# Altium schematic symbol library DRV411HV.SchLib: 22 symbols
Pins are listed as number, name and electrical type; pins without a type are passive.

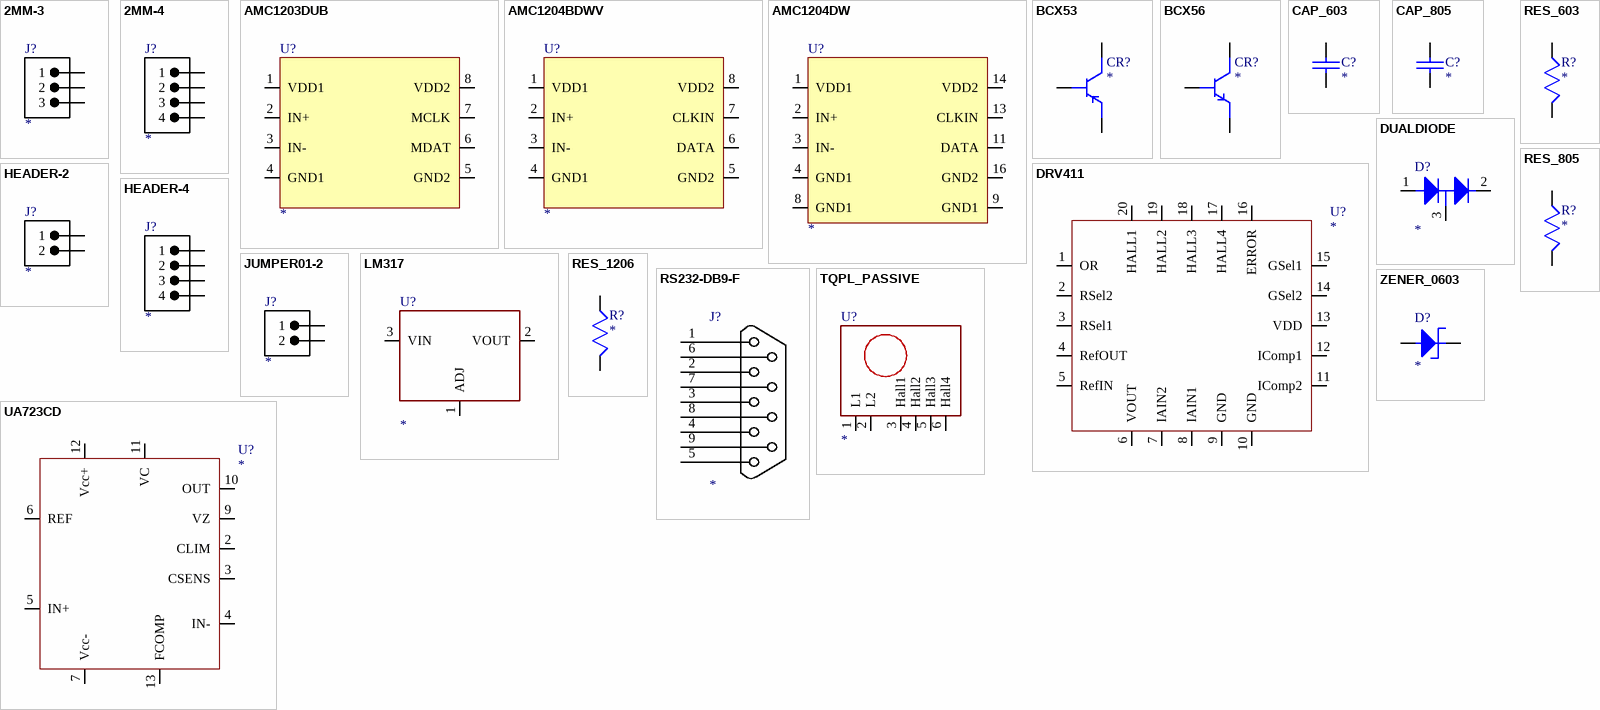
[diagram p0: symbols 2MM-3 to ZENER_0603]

## 2MM-3
designator J?
3x1 2mm male header
footprint 2MM1X3
pins: 1, 2, 3

## 2MM-4
designator J?
4x1 2mm male header
footprint 2MM1X4
pins: 1, 2, 3, 4

## AMC1203DUB
designator U?
AMC1203DUB
footprint 8-SOP(DUB)
pins: 1 VDD1, 2 IN+, 3 IN-, 4 GND1, 5 GND2, 6 MDAT, 7 MCLK, 8 VDD2

## AMC1204BDWV
designator U?
AMC1204BDWV
footprint 8-SOP(DWV)
pins: 1 VDD1, 2 IN+, 3 IN-, 4 GND1, 5 GND2, 6 DATA, 7 CLKIN, 8 VDD2

## AMC1204DW
designator U?
AMC1204DW
footprint 16-TSSOP(DW)
pins: 1 VDD1, 2 IN+, 3 IN-, 4 GND1, 8 GND1, 9 GND1, 11 DATA, 13 CLKIN, 14 VDD2, 16 GND2

## BCX53
designator CR?
Medium Power PNP Transistor
footprint SOT89
pins: 1, 2, 3

## BCX56
designator CR?
NPN Medium Power Transistor
footprint SOT89
pins: 1, 2, 3

## CAP_603
designator C?
Multilayer Ceramic - 0603Size
footprint 0603
pins: 1, 2

## CAP_805
designator C?
Multilayer Ceramic - 0805 Size
footprint 0805
pins: 1, 2

## DRV411
designator U?
DRV411
footprint 20-TSSOP(PWP)
pins: 1 OR, 2 RSel2, 3 RSel1, 4 RefOUT, 5 RefIN, 6 VOUT, 7 IAIN2, 8 IAIN1, 9 GND, 10 GND, 11 IComp2, 12 IComp1, 13 VDD, 14 GSel2, 15 GSel1, 16 ERROR, 17 HALL4, 18 HALL3, 19 HALL2, 20 HALL1

## DUALDIODE
designator D?
Dual Schotkey
footprint SOT23
pins: 1, 2, 3

## HEADER-2
designator J?
3x1 100 mil male header
footprint HDR1X2
pins: 1, 2

## HEADER-4
designator J?
4x1 100 mil male header
footprint HDR1X4
pins: 1, 2, 3, 4

## JUMPER01-2
designator J?
2x1 0.1 inch female header
footprint 10THINx2
pins: 1, 2

## LM317
designator U?
LM317S
footprint 3-TO263(KTT)
pins: 1 ADJ, 2 VOUT, 3 VIN

## RES_603
designator R?
Resister - 0603Size
footprint 0603
pins: 1, 2

## RES_805
designator R?
Resister - 0805Size
footprint 0805
pins: 1, 2

## RES_1206
designator R?
Resister - 1206Size
footprint 1206
pins: 1, 2

## RS232-DB9-F
designator J?
footprint DB9FL
pins: 1 DCD, 2 RD, 3 TD, 4 DTR, 5 SG, 6 DSR, 7 RTS, 8 CTS, 9 RI

## TQPL_PASSIVE
designator U?
TopStek Passive Hall Sensor
footprint TQPL_Passive
pins: 1 L1, 2 L2, 3 Hall1, 4 Hall2, 5 Hall3, 6 Hall4

## UA723CD
designator U?
uA723CD
footprint 14-SOP(D)
pins: 2 CLIM, 3 CSENS, 4 IN-, 5 IN+, 6 REF, 7 Vcc-, 9 VZ, 10 OUT, 11 VC, 12 Vcc+, 13 FCOMP

## ZENER_0603
designator D?
Zener Diode - 160mW - 0603 Size
footprint 0603_DIO
pins: 1, 2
